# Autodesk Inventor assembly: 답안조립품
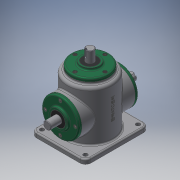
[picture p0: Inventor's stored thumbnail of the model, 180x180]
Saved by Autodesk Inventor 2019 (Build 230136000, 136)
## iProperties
Created: 2020-12
Part Number: 답안조립품
Material: 일반
Document SubType Name: Assembly
Designer: jun-1-10
Author: jun-1-10
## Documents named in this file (16)
- C:\Users\jun-1-10\Desktop\701207V1006\답안조립품.iam
- C:\Users\jun-1-10\Desktop\701207V1006\답안본체.ipt
- C:\Users\jun-1-10\Desktop\701207V1006\메인 베벨기어.ipt
- C:\Users\jun-1-10\Desktop\701207V1006\메인 축.ipt
- 메인 축.ipt
- C:\Users\jun-1-10\Desktop\701207V1006\베어링 6203.ipt
- C:\Users\jun-1-10\Desktop\701207V1006\볼트 M4.ipt
- 볼트 M4.ipt
- C:\Users\jun-1-10\Desktop\701207V1006\서브 베벨기어.ipt
- C:\Users\jun-1-10\Desktop\701207V1006\서브 축.ipt
- 서브 축.ipt
- C:\Users\jun-1-10\Desktop\701207V1006\오일 실.ipt
- 오일 실.ipt
- C:\Users\jun-1-10\Desktop\701207V1006\커버.ipt
- C:\Users\jun-1-10\Desktop\701207V1006\키 4x4.ipt
- C:\Users\jun-1-10\Desktop\701207V1006\키 5x5.ipt
